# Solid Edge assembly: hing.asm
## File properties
Author: Mac
Template: Normal.asm
Last saved by: Mac
Revision: 4
Application: Solid Edge
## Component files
hing.psm
hingepolt.par
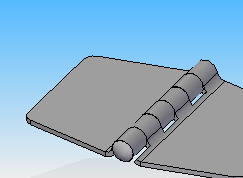
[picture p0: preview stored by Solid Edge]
